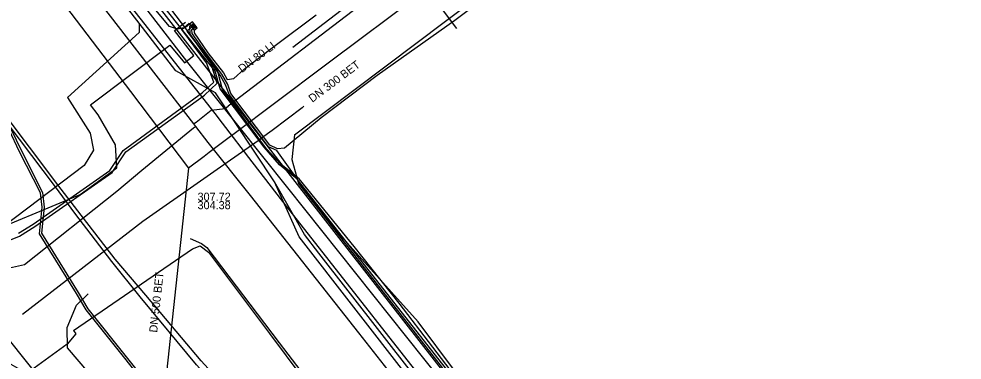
# Model space of a CAD drawing. Extents: x -600391 to -599491, y -1160176 to -1159402.
# Drawn here: x -600242.3 to -600149.1, y -1160109.3 to -1160075.6 of the extents above; entities that cross this region are included whole.
import ezdxf

# ---------------------------------------------------------------- set-up
doc = ezdxf.new("R2010")
doc.units = 0
for name, color, linetype in [('28', 7, 'Continuous'), ('CETIN_linie', 7, 'Continuous'), ('Vrstva 12', 7, 'Continuous'), ('Vrstva 13', 7, 'Continuous'), ('Vrstva 15', 7, 'Continuous'), ('Vrstva 16', 7, 'Continuous'), ('Vrstva 19', 7, 'Continuous'), ('Vrstva 42', 7, 'Continuous'), ('Vrstva 43', 7, 'Continuous'), ('Vrstva 44', 7, 'Continuous'), ('Vrstva 55', 7, 'Continuous'), ('Vrstva 58', 7, 'Continuous'), ('Vrstva 9', 7, 'Continuous')]:
    doc.layers.add(name, color=color, linetype=linetype)

# ---------------------------------------------------------------- blocks, each defined once
blk = doc.blocks.new('NN620')
at = {"layer": '28'}
for points in [[(0.75, 0), (-0.75, 0)], [(-0.75, 0), (-0.75, -0.75)], [(0.75, -0.75), (0.75, 0)], [(-0.75, -0.75), (0.75, -0.75)], [(0.37, -0.18), (-0.38, -0.18)], [(-0.38, -0.18), (-0.38, -0.56)], [(-0.38, -0.56), (0.37, -0.56)], [(0.32, -0.23), (-0.33, -0.23)], [(-0.33, -0.23), (-0.33, -0.51)], [(-0.33, -0.51), (0.32, -0.51)], [(0.27, -0.27), (-0.28, -0.27)], [(-0.28, -0.27), (-0.28, -0.46)], [(-0.28, -0.46), (0.27, -0.46)], [(0.23, -0.32), (-0.23, -0.32)], [(-0.23, -0.32), (-0.23, -0.42)], [(-0.23, -0.42), (0.23, -0.42)], [(-0.19, -0.37), (0.19, -0.37)], [(0.23, -0.42), (0.23, -0.32)], [(0.27, -0.46), (0.27, -0.27)], [(0.32, -0.51), (0.32, -0.23)], [(0.37, -0.56), (0.37, -0.18)]]:
    blk.add_lwpolyline(points, dxfattribs=at)

msp = doc.modelspace()

# ---------------------------------------------------------------- linework, layer by layer
at = {"layer": 'CETIN_linie'}
for p, q in [((-600215.11, -1160087.04), (-600186.34, -1160065.31)), ((-600208.44, -1160099.88), (-600194.75, -1160117.41)), ((-600236.95, -1160106.39), (-600236.72, -1160106.71))]:
    msp.add_line(p, q, dxfattribs=at)
for points in [[(-600267.76, -1160025.17), (-600244.25, -1160055.86), (-600225.67, -1160079.89), (-600215.81, -1160092.29), (-600192.29, -1160121.78), (-600180.19, -1160137.43), (-600168.62, -1160151.9), (-600165.36, -1160149.31), (-600163.31, -1160147.71)], [(-600215.11, -1160087.04), (-600215.36, -1160089.49), (-600214.71, -1160091.85), (-600208.44, -1160099.88)], [(-600225.43, -1160097.28), (-600224.31, -1160097.79), (-600223.76, -1160098.18), (-600216.62, -1160107.61), (-600209.03, -1160117.53), (-600185.54, -1160147.75), (-600167.22, -1160171.18)], [(-600236.95, -1160106.39), (-600225.2, -1160098.31), (-600224.42, -1160098.02), (-600223.61, -1160098.65), (-600217.59, -1160106.66), (-600212.75, -1160113.15), (-600211.24, -1160114.99), (-600205.8, -1160122.19), (-600205.52, -1160124.13), (-600204.93, -1160125.7), (-600202.44, -1160129.78), (-600199.68, -1160131.86), (-600196.72, -1160133.45), (-600190.22, -1160141.6), (-600189.29, -1160143.37), (-600186.42, -1160146.92), (-600183.71, -1160150.47)], [(-600236.72, -1160106.71), (-600237.57, -1160107.73), (-600241.19, -1160110.36), (-600241.71, -1160110.53), (-600244.04, -1160109.21), (-600244.88, -1160109.24), (-600251.06, -1160114.23), (-600251.34, -1160113.88), (-600256.71, -1160110.78), (-600256.89, -1160110.66)]]:
    msp.add_lwpolyline(points, dxfattribs=at)
at = {"layer": 'Vrstva 13'}
for p, q in [((-600200.61, -1160068.13), (-600221.66, -1160084.2)), ((-600225.09, -1160085.97), (-600224.84, -1160085.79)), ((-600225.09, -1160085.97), (-600224.89, -1160086.22)), ((-600225.08, -1160086.37), (-600224.89, -1160086.22))]:
    msp.add_line(p, q, dxfattribs=at)
for points in [[(-600308.304, -1159974.747), (-600310.606, -1159976.582), (-600309.22, -1159978.29), (-600300.55, -1159989.29), (-600296.77, -1159994.11), (-600294.38, -1159997.18), (-600292.26, -1159999.96), (-600280.7, -1160014.54), (-600273.1, -1160024.31), (-600254.85, -1160047.91), (-600240.71, -1160065.868), (-600236.26, -1160071.52), (-600225.09, -1160085.97)], [(-600269.901, -1160024.72), (-600239.13, -1160064.49), (-600235.85, -1160068.55), (-600222.987, -1160084.95), (-600222.259, -1160085.895), (-600219.33, -1160089.71)], [(-600364.61, -1160031.76), (-600357.966, -1160036.106), (-600353.754, -1160038.902), (-600347.829, -1160042.833), (-600335.57, -1160051.15), (-600331.773, -1160053.742), (-600316.284, -1160064.166), (-600315.765, -1160064.506), (-600310.155, -1160068.201), (-600292.01, -1160080.31), (-600289.22, -1160082.13), (-600264.27, -1160099.11), (-600257.808, -1160103.361), (-600247.146, -1160101.039), (-600241.8, -1160099.846), (-600232.66, -1160092.61)], [(-600224.84, -1160085.79), (-600223.33, -1160084.62), (-600221.97, -1160084.45), (-600221.66, -1160084.2)], [(-600232.66, -1160092.61), (-600230.19, -1160090.54), (-600225.08, -1160086.37)], [(-600224.89, -1160086.22), (-600223.66, -1160087.79), (-600219.48, -1160093.03), (-600208.78, -1160106.62), (-600205.17, -1160111.23), (-600199.082, -1160119.045), (-600197.73, -1160120.78), (-600193.89, -1160125.68), (-600192.77, -1160127.135), (-600192.48, -1160127.51), (-600191.95, -1160128.2), (-600186.44, -1160135.41), (-600179, -1160144.94), (-600171.696, -1160154.271), (-600171.65, -1160154.33), (-600167.97, -1160159.08), (-600165.22, -1160162.741), (-600160.551, -1160168.918), (-600159.86, -1160169.84), (-600157.58, -1160168), (-600157.9, -1160167.54)], [(-600219.33, -1160089.71), (-600216.29, -1160093.64), (-600198.339, -1160116.482), (-600192.274, -1160124.216), (-600191.1, -1160125.733), (-600170.22, -1160153.004), (-600164.3, -1160160.4), (-600163.344, -1160161.593), (-600158.656, -1160167.697)]]:
    msp.add_lwpolyline(points, dxfattribs=at)
at = {"layer": 'Vrstva 16'}
for points in [[(-600149.134, -1160176.079), (-600149.77, -1160175.26), (-600153.28, -1160170.92), (-600160.82, -1160161.59), (-600162.37, -1160159.57), (-600191.81, -1160121.42), (-600215.03, -1160091.66), (-600218.37, -1160087.39), (-600241.27, -1160058.04), (-600268.45, -1160023.15), (-600268.66, -1160022.86), (-600279.96, -1160008.45), (-600285.15, -1160001.76), (-600292.76, -1159991.95), (-600306.26, -1159974.55), (-600310.89, -1159968.58), (-600323.17, -1159952.95), (-600331.19, -1159942.75), (-600331.3, -1159942.61), (-600336.91, -1159935.47), (-600352.95, -1159915.04), (-600356.32, -1159910.78), (-600372.09, -1159890.83), (-600376.451, -1159885.301)], [(-600214.187, -1160084.2), (-600214.35, -1160084.382), (-600217.33, -1160086.61)], [(-600217.33, -1160086.61), (-600218.37, -1160087.39)], [(-600242.003, -1160104.763), (-600230.09, -1160095.57), (-600218.37, -1160087.39)]]:
    msp.add_lwpolyline(points, dxfattribs=at)
at = {"layer": 'Vrstva 19'}
for points in [[(-600201.2, -1160073.73), (-600199.1, -1160076.53)], [(-600187.404, -1160176.079), (-600188.24, -1160174.94), (-600189.714, -1160173.065), (-600189.932, -1160172.795), (-600192.198, -1160170.051), (-600195.116, -1160165.979), (-600202.322, -1160156.29), (-600207.254, -1160150.47), (-600208.079, -1160149.427), (-600211.081, -1160145.492), (-600214.3, -1160141.284), (-600216.14, -1160138.91), (-600219.326, -1160134.724), (-600220.15, -1160133.78), (-600222.55, -1160133.45), (-600230.24, -1160123.78), (-600234.667, -1160118.276), (-600235.82, -1160116.58), (-600239.7, -1160111.77), (-600241.589, -1160109.434), (-600248.735, -1160100.513)]]:
    msp.add_lwpolyline(points, dxfattribs=at)
at = {"layer": 'Vrstva 42'}
for points in [[(-600225.469, -1160076.111), (-600225.89, -1160076.46), (-600226.66, -1160076.6), (-600227.46, -1160076.33), (-600228.81, -1160074.72), (-600233.25, -1160068.86), (-600237.21, -1160063.66), (-600239.359, -1160060.587), (-600238.62, -1160059.54), (-600238.038, -1160058.819), (-600237.99, -1160058.6), (-600238.193, -1160058.693), (-600238.78, -1160059.42), (-600239.511, -1160060.456), (-600240.36, -1160060.05), (-600241.6, -1160058.84), (-600245.71, -1160053.3)], [(-600192.95, -1160070.97), (-600199.27, -1160075.75), (-600206.93, -1160081.17), (-600212.48, -1160085.37), (-600216.1, -1160088.35), (-600216.78, -1160088.42), (-600217.546, -1160088.079), (-600221.4, -1160082.973), (-600221.702, -1160082.082), (-600222.3, -1160081.04), (-600223.82, -1160079.06), (-600225.23, -1160077.04), (-600225.238, -1160076.641), (-600225.129, -1160076.552)], [(-600225.036, -1160076.686), (-600225.031, -1160076.976), (-600223.659, -1160078.942), (-600222.133, -1160080.929), (-600221.748, -1160081.596), (-600221.09, -1160081.49), (-600220.07, -1160080.57), (-600216.88, -1160078.12), (-600212.98, -1160075.18)], [(-600266.079, -1160106.619), (-600265.38, -1160105.565), (-600271.011, -1160101.521), (-600266.643, -1160095.207), (-600261.696, -1160098.394), (-600258.683, -1160100.256), (-600256.174, -1160100.737), (-600253.882, -1160100.307), (-600246.75, -1160097.303), (-600236.294, -1160092.947), (-600232.661, -1160090.292), (-600232.796, -1160088.04), (-600234.517, -1160085.087), (-600235.283, -1160084.082), (-600227.433, -1160078.187), (-600225.976, -1160079.933), (-600225.059, -1160079.225), (-600226.98, -1160076.754), (-600225.887, -1160075.904)], [(-600243.487, -1160097.564), (-600242.279, -1160097.043), (-600240.773, -1160096.113), (-600233.14, -1160090.784), (-600231.776, -1160088.721), (-600224.013, -1160083.112), (-600222.767, -1160081.95), (-600223.444, -1160079.738), (-600225.714, -1160076.801), (-600225.24, -1160076.372)], [(-600242.399, -1160096.765), (-600240.938, -1160095.862), (-600233.359, -1160090.571), (-600232.046, -1160088.586), (-600224.197, -1160082.873), (-600223.091, -1160081.842), (-600223.795, -1160079.941), (-600226.259, -1160076.625), (-600225.525, -1160076.016)], [(-600199.31, -1160110.32), (-600202.9, -1160105.51), (-600210.78, -1160096.73), (-600214.05, -1160092.52), (-600216.865, -1160088.6), (-600217.674, -1160088.241), (-600221.58, -1160083.067), (-600221.887, -1160082.16), (-600222.467, -1160081.151), (-600223.981, -1160079.178), (-600225.429, -1160077.104), (-600225.442, -1160076.323), (-600225.355, -1160076.25)]]:
    msp.add_lwpolyline(points, dxfattribs=at)
at = {"layer": 'Vrstva 44'}
for points in [[(-600160.621, -1160151.483), (-600164.61, -1160154.49), (-600164.75, -1160154.55), (-600164.92, -1160154.53), (-600165.13, -1160154.43), (-600167.52, -1160151.31), (-600171.43, -1160146.29), (-600175.79, -1160140.75), (-600179.33, -1160136.25), (-600182.1, -1160132.67), (-600186.25, -1160127.32), (-600191.99, -1160119.95), (-600198.1, -1160112.38), (-600204.78, -1160103.69), (-600209.2, -1160098.08), (-600214.66, -1160091.39), (-600216.44, -1160089.98), (-600217.86, -1160088.43), (-600221.95, -1160082.93), (-600222.23, -1160082.56), (-600222.64, -1160080.93), (-600222.7, -1160080.75), (-600225.12, -1160077.51), (-600230.17, -1160070.83)], [(-600242.63, -1160155.71), (-600223.03, -1160136.01), (-600220.97, -1160135.94), (-600220.38, -1160136.2), (-600217.06, -1160140.66), (-600216.58, -1160141), (-600216.16, -1160141.12), (-600215.39, -1160140.83), (-600212.419, -1160138.452), (-600206.12, -1160133.83), (-600205.884, -1160133.585), (-600205.79, -1160133.14), (-600205.95, -1160132.69), (-600205.91, -1160132.49), (-600207.54, -1160130.56), (-600211.43, -1160125.14), (-600215.4, -1160120.28), (-600219.56, -1160115.55), (-600224.8, -1160109.76), (-600230.36, -1160103.04), (-600233.16, -1160099.57), (-600236.83, -1160094.8), (-600238.73, -1160092.17), (-600250.56, -1160076.56)], [(-600215.22, -1160141.01), (-600212.24, -1160138.67), (-600205.87, -1160134.37), (-600205.43, -1160133.8), (-600205.48, -1160133.24), (-600205.5, -1160132.12), (-600211.27, -1160124.94), (-600215.15, -1160120.07), (-600219.05, -1160115.15), (-600224.34, -1160109.38), (-600229.81, -1160102.89), (-600232.83, -1160099.34), (-600236.52, -1160094.54), (-600238.5, -1160091.97), (-600249.74, -1160077.1)], [(-600242.907, -1160155.529), (-600241.127, -1160154.969), (-600222.537, -1160136.669), (-600221.757, -1160136.679), (-600220.547, -1160137.039), (-600217.127, -1160140.649), (-600216.251, -1160140.666), (-600215.214, -1160139.705), (-600212.809, -1160137.597), (-600212.69, -1160136.953), (-600213.922, -1160132.479), (-600215.387, -1160128.415), (-600217.767, -1160124.889), (-600219.562, -1160124.53), (-600235.699, -1160104.336), (-600236.662, -1160102.721), (-600240.31, -1160096.813), (-600240.038, -1160094.179), (-600240.194, -1160092.788), (-600242.277, -1160088.713), (-600243.305, -1160086.547)], [(-600243.129, -1160086.451), (-600242.097, -1160088.625), (-600240, -1160092.73), (-600239.836, -1160094.179), (-600240.104, -1160096.765), (-600236.492, -1160102.617), (-600235.535, -1160104.222), (-600219.452, -1160124.348), (-600217.647, -1160124.709), (-600215.207, -1160128.323), (-600213.732, -1160132.419), (-600212.484, -1160136.945), (-600212.625, -1160137.701), (-600215.08, -1160139.853), (-600216.092, -1160140.791), (-600215.887, -1160142.459), (-600213.627, -1160145.479), (-600205.577, -1160155.769), (-600190.627, -1160175.369), (-600190.098, -1160176.079)]]:
    msp.add_lwpolyline(points, dxfattribs=at)
at = {"layer": 'Vrstva 55'}
for points in [[(-600159.37, -1160161.02), (-600163.57, -1160162.94), (-600178.28, -1160142.933), (-600197.299, -1160118.521), (-600212.697, -1160098.724), (-600214.119, -1160096.9), (-600217.08, -1160091.68), (-600222.93, -1160082.91), (-600226.85, -1160080.74), (-600230.45, -1160076.02), (-600247.641, -1160053.846), (-600267.85, -1160028.08), (-600281.812, -1160010.273), (-600299.508, -1159987.183)], [(-600161.26, -1160037.75), (-600161.7, -1160037.83), (-600177.432, -1160049.815), (-600189.48, -1160058.31), (-600198.553, -1160065.567), (-600215.27, -1160078.43)], [(-600159.37, -1160161.02), (-600162.95, -1160162.67), (-600163.57, -1160162.94), (-600178.36, -1160142.986), (-600192.39, -1160125.04), (-600203.84, -1160111.02), (-600214.66, -1160097.11), (-600217.08, -1160091.68), (-600222.93, -1160082.91), (-600226.85, -1160080.74), (-600230.45, -1160076.02), (-600230.45, -1160076.94), (-600237.55, -1160083.37), (-600235.29, -1160086.88), (-600234.96, -1160088.55), (-600235.88, -1160090.06), (-600243.77, -1160096.03)], [(-600183.385, -1160176.079), (-600190.519, -1160167.28), (-600203.613, -1160150.715), (-600217.299, -1160134.673), (-600230.074, -1160116.863), (-600237.553, -1160108.104), (-600237.57, -1160106.07), (-600236.65, -1160103.88), (-600235.511, -1160102.748)]]:
    msp.add_lwpolyline(points, dxfattribs=at)
at = {"layer": 'Vrstva 58'}
msp.add_lwpolyline([(-600152.816, -1160155.247), (-600149.861, -1160159.292), (-600149.734, -1160159.861), (-600149.948, -1160160.271), (-600152.824, -1160162.001), (-600154.716, -1160162.875), (-600156.47, -1160162.913), (-600156.971, -1160162.768), (-600158.029, -1160162.46), (-600159.391, -1160161.608), (-600159.936, -1160160.912), (-600162.585, -1160157.659), (-600164.043, -1160155.634), (-600165.021, -1160154.824), (-600214.84, -1160091.439), (-600216.589, -1160090.02), (-600218.109, -1160088.272), (-600222.441, -1160082.519), (-600222.948, -1160080.77), (-600256.663, -1160038.315), (-600300.347, -1159981.753)], dxfattribs=at)
at = {"layer": 'Vrstva 9'}
msp.add_line((-600225.57, -1160090.33), (-600228.619, -1160118.508), dxfattribs=at)
for points in [[(-600255.69, -1160050.79), (-600245.873, -1160063.677), (-600231.33, -1160082.769), (-600225.57, -1160090.33)], [(-600198.69, -1160070.16), (-600209.962, -1160078.618), (-600210.2, -1160078.797), (-600218.793, -1160085.245), (-600219.23, -1160085.573), (-600223.532, -1160088.801), (-600224.045, -1160089.186), (-600225.57, -1160090.33)]]:
    msp.add_lwpolyline(points, dxfattribs=at)

# ---------------------------------------------------------------- block references
at = {"layer": 'Vrstva 43', "xscale": 0.5, "yscale": 0.5, "rotation": 128}
msp.add_blockref('NN620', (-600225.24, -1160076.42), dxfattribs=at)

# ---------------------------------------------------------------- texts
at = {"layer": 'Vrstva 12'}
for s, rotation, p in [('DN 300 BET', 36.89848, (-600213.35, -1160083.892)), ('DN 500 BET', 83.82373, (-600228.684, -1160106.61))]:
    msp.add_text(s, height=0.8, rotation=rotation, dxfattribs=at).set_placement(p)
for s, p in [('307.72', (-600224.689, -1160093.562)), ('304.38', (-600224.689, -1160094.394))]:
    msp.add_text(s, height=0.8, dxfattribs=at).set_placement(p)
at = {"layer": 'Vrstva 15'}
msp.add_text('DN 80 LI', height=0.8, rotation=36.89848, dxfattribs=at).set_placement((-600220.293, -1160080.955))

doc.saveas('drawing.dxf')
